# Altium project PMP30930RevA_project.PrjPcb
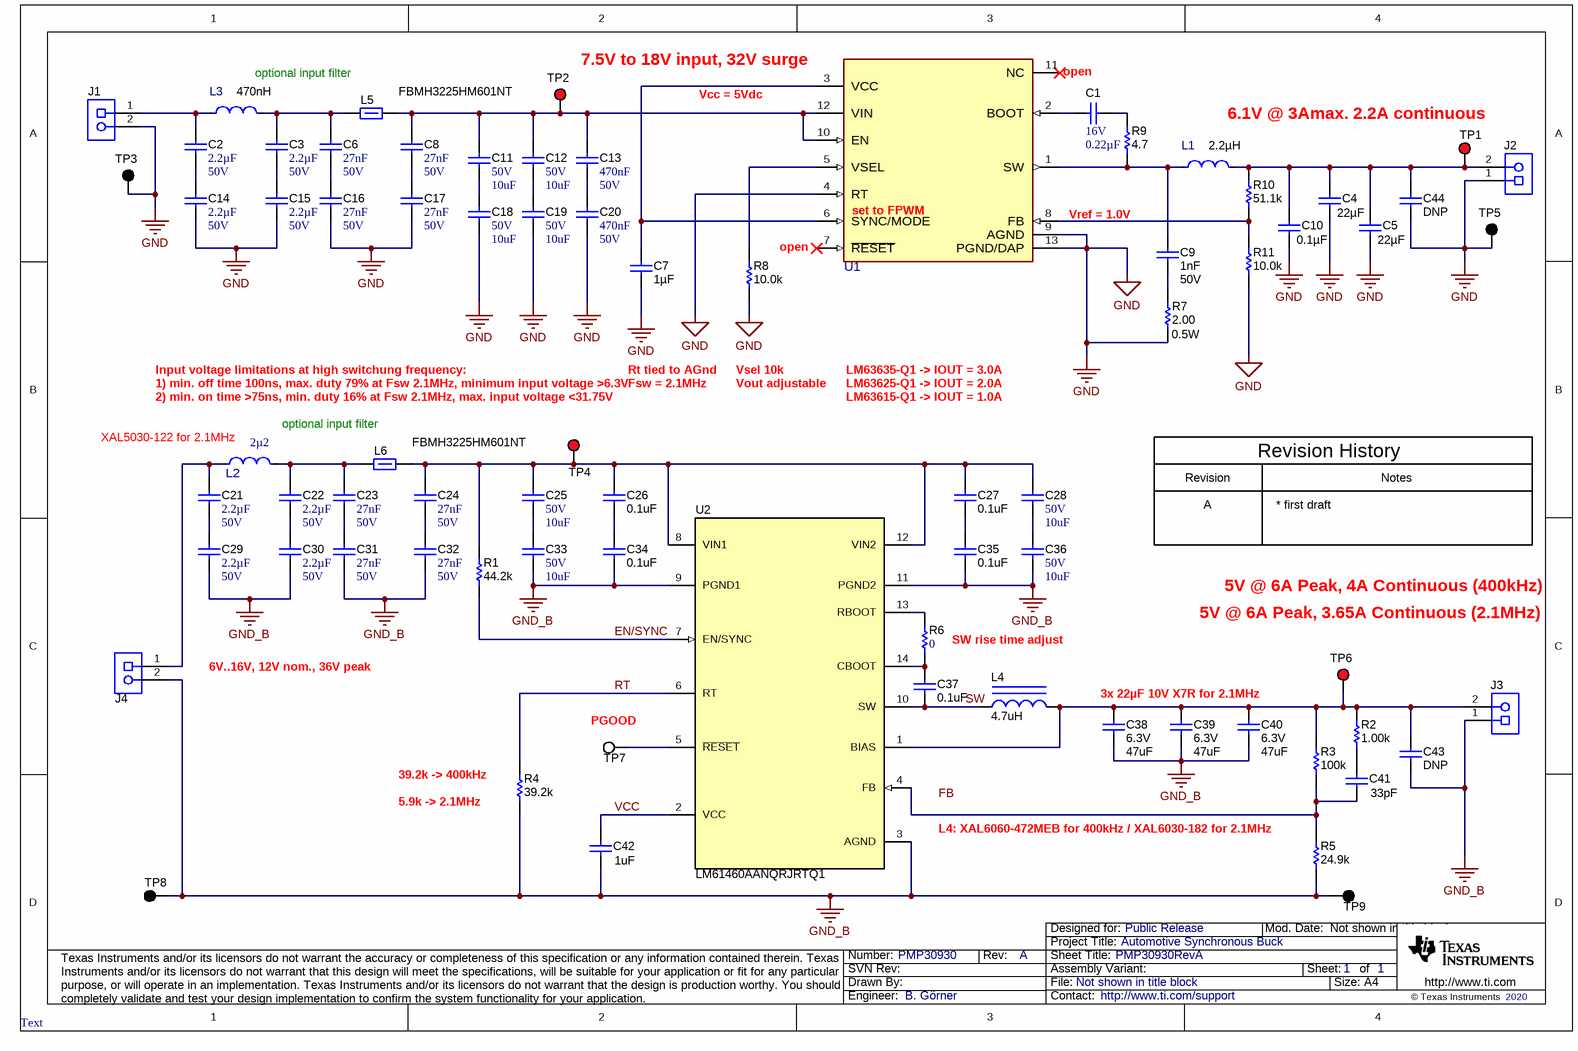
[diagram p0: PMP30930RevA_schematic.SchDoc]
CopyrightYear: 2020; PCB_Rev: A; PRJ_Customer: Public Release; PRJ_Engineer: B. Görner; PRJ_Number: PMP30930; PRJ_Title: Automotive Synchronous Buck; SCH_Rev: A; SCH_Title: asdf; TechSupport: http://www.ti.com/support; TID: N/A
2 sheets, 112 parts. Net scope: global (net labels, ports and power ports of the same name join across sheets).
Board file: PMP30930RevA_board.PcbDoc
Sheets:
  PMP30930RevA_schematic.SchDoc
  PMP30930RevA_schematic_2.SchDoc

## Sheet PMP30930RevA_schematic.SchDoc: PMP30930RevA
size A4; Date: Not shown in title block; ApprovedBy: Not shown in title block; CheckedBy: Not shown in title block; Author: Not shown in title block; CompanyName: Not shown in title block; Engineer: Not shown in title block; Organization: Not shown in title block; Address1: Not shown in title block; Address2: Not shown in title block; Address3: Not shown in title block; Address4: Not shown in title block; DocumentNumber: 1; Revision: Use project parameter SCH_Rev; SheetNumber: 1; SheetTotal: 1; PageSetup: Record=PageOptions¦CenterHorizontal=True¦CenterVertical=True¦PrintScale=0.70¦XCorrection=1.00¦YCorrection=1.00¦PrintKind=0¦BorderSize=5000000¦LeftOffset=0¦BottomOffset=0¦Orientation=2¦PaperLength=1000¦PaperWidth=1000¦Scale=100¦PaperSource=15¦PrintQuality=600¦MediaType=1¦DitherType=10¦PaperKind=A4¦PrintScaleMode=1

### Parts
C1  VDC_V: 16V  ValueDisplayed: 0.22µF  [0402]  (hidden comment: GCM155R71C224KE02D)
C2  Cap_F: 2.2µF  VDC_V: 50V  [0805_HV]  (hidden comment: CGA4J3X7R1H225K125AB)
C3  Cap_F: 2.2µF  VDC_V: 50V  [0805_HV]  (hidden comment: CGA4J3X7R1H225K125AB)
C4  ValueDisplayed: 22µF  [1210_270]  (hidden comment: GRM32ER71E226KE15L)
C5  ValueDisplayed: 22µF  [1210_270]  (hidden comment: GRM32ER71E226KE15L)
C6  Cap_F: 27nF  VDC_V: 50V  [0603]  (hidden comment: 06035C273K4T2A)
C7  ValueDisplayed: 1µF  [0603]  (hidden comment: GCM188R71E105KA64D)
C8  Cap_F: 27nF  VDC_V: 50V  [0603]  (hidden comment: 06035C273K4T2A)
C9  Cap_F: 1nF  VDC_V: 50V  [0603]  (hidden comment: GRM188R71H102KA01D)
C10  ValueDisplayed: 0.1µF  [0603]  (hidden comment: GRM188R71E104KA01D)
C11  VDC_V: 50V  ValueDisplayed: 10uF  [1210_270]  (hidden comment: GRM32ER71H106KA12L)
C12  VDC_V: 50V  ValueDisplayed: 10uF  [1210_270]  (hidden comment: GRM32ER71H106KA12L)
C13  Cap_F: 470nF  VDC_V: 50V  [0603]  (hidden comment: CGA3E3X7R1H474K080AE)
C14  Cap_F: 2.2µF  VDC_V: 50V  [0805_HV]  (hidden comment: CGA4J3X7R1H225K125AB)
C15  Cap_F: 2.2µF  VDC_V: 50V  [0805_HV]  (hidden comment: CGA4J3X7R1H225K125AB)
C16  Cap_F: 27nF  VDC_V: 50V  [0603]  (hidden comment: 06035C273K4T2A)
C17  Cap_F: 27nF  VDC_V: 50V  [0603]  (hidden comment: 06035C273K4T2A)
C18  VDC_V: 50V  ValueDisplayed: 10uF  [1210_270]  (hidden comment: GRM32ER71H106KA12L)
C19  VDC_V: 50V  ValueDisplayed: 10uF  [1210_270]  (hidden comment: GRM32ER71H106KA12L)
C20  Cap_F: 470nF  VDC_V: 50V  [0603]  (hidden comment: CGA3E3X7R1H474K080AE)
C21  Cap_F: 2.2µF  VDC_V: 50V  [0805_HV]  (hidden comment: CGA4J3X7R1H225K125AB)
C22  Cap_F: 2.2µF  VDC_V: 50V  [0805_HV]  (hidden comment: CGA4J3X7R1H225K125AB)
C23  Cap_F: 27nF  VDC_V: 50V  [0603]  (hidden comment: 06035C273K4T2A)
C24  Cap_F: 27nF  VDC_V: 50V  [0603]  (hidden comment: 06035C273K4T2A)
C25  VDC_V: 50V  ValueDisplayed: 10uF  [1210_270]  (hidden comment: GRM32ER71H106KA12L)
C26  ValueDisplayed: 0.1uF  [0402S]  (hidden comment: CGA2B3X7R1H104K050BB)
C27  ValueDisplayed: 0.1uF  [0402S]  (hidden comment: CGA2B3X7R1H104K050BB)
C28  VDC_V: 50V  ValueDisplayed: 10uF  [1210_270]  (hidden comment: GRM32ER71H106KA12L)
C29  Cap_F: 2.2µF  VDC_V: 50V  [0805_HV]  (hidden comment: CGA4J3X7R1H225K125AB)
C30  Cap_F: 2.2µF  VDC_V: 50V  [0805_HV]  (hidden comment: CGA4J3X7R1H225K125AB)
C31  Cap_F: 27nF  VDC_V: 50V  [0603]  (hidden comment: 06035C273K4T2A)
C32  Cap_F: 27nF  VDC_V: 50V  [0603]  (hidden comment: 06035C273K4T2A)
C33  VDC_V: 50V  ValueDisplayed: 10uF  [1210_270]  (hidden comment: GRM32ER71H106KA12L)
C34  ValueDisplayed: 0.1uF  [0402S]  (hidden comment: CGA2B3X7R1H104K050BB)
C35  ValueDisplayed: 0.1uF  [0402S]  (hidden comment: CGA2B3X7R1H104K050BB)
C36  VDC_V: 50V  ValueDisplayed: 10uF  [1210_270]  (hidden comment: GRM32ER71H106KA12L)
C37  ValueDisplayed: 0.1uF  [0402S]  (hidden comment: C0402C104K4RACAUTO)
C38  VDC_V: 6.3V  ValueDisplayed: 47uF  [1210_270]  (hidden comment: GCM32ER70J476KE19L)
C39  VDC_V: 6.3V  ValueDisplayed: 47uF  [1210_270]  (hidden comment: GCM32ER70J476KE19L)
C40  VDC_V: 6.3V  ValueDisplayed: 47uF  [1210_270]  (hidden comment: GCM32ER70J476KE19L)
C41  ValueDisplayed: 33pF  [0402S]  (hidden comment: C0402C330J5GACAUTO)
C42  ValueDisplayed: 1uF  [0603S]  (hidden comment: GCM188R71C105KA64D)
C43  ValueDisplayed: DNP  [0402S]  (hidden comment: CGA2B3X7R1H104K050BB)
C44  ValueDisplayed: DNP  [0402S]  (hidden comment: CGA2B3X7R1H104K050BB)
J1  ED555/2DS  [TERM_BLK_ED555-2DS]  (value not drawn)
J2  ED555/2DS  [TERM_BLK_ED555-2DS]  (value not drawn)
J3  ED555/2DS  [TERM_BLK_ED555-2DS]  (value not drawn)
J4  ED555/2DS  [TERM_BLK_ED555-2DS]  (value not drawn)
L1  Ind_H: 2.2µH  [FP-XGL4020-222MEC_SMT_4MM0_4MM0-MFG]  (hidden comment: XGL4020-222MEC)
L2  XEL5030-222MEB  [FP-XEL5030-222MEB_SMT_INDUCTOR_5MM28_5MM48-MFG]  (value not drawn)
L3  Ind_H: 470nH  [FP-XGL4020-471MEC_SMT_4MM0_4MM0-MFG]  (hidden comment: XGL4020-471MEC)
L4  ValueDisplayed: 4.7uH  [XAL6060]  (hidden comment: XAL6060-472MEB)
L5  FBMH3225HM601NT  [1210_280]
L6  FBMH3225HM601NT  [1210_280]
R1  ValueDisplayed: 44.2k  [0402S]  (hidden comment: CRCW040244K2FKED)
R2  ValueDisplayed: 1.00k  [0402S]  (hidden comment: CRCW04021K00FKED)
R3  ValueDisplayed: 100k  [0402S]  (hidden comment: RMCF0402FT100K)
R4  ValueDisplayed: 39.2k  [0402S]  (hidden comment: CRCW040239K2FKED)
R5  ValueDisplayed: 24.9k  [0402S]  (hidden comment: CRCW040224K9FKED)
R6  ValueDisplayed: 0  [0402S]  (hidden comment: CRCW04020000Z0EDHP)
R7  ValueDisplayed: 2.00  Value2: 0.5W  [0805_HV]  (hidden comment: CRCW08052R00FKEAHP)
R8  ValueDisplayed: 10.0k  [0402]  (hidden comment: CRCW040210K0FKED)
R9  ValueDisplayed: 4.7  [0603]  (hidden comment: CRCW06034R70JNEA)
R10  ValueDisplayed: 51.1k  [0402]  (hidden comment: CRCW040251K1FKED)
R11  ValueDisplayed: 10.0k  [0402]  (hidden comment: CRCW040210K0FKED)
TP1  5010  [Keystone5010]  (value not drawn)
TP2  5010  [Keystone5010]  (value not drawn)
TP3  5011  [Keystone5011]  (value not drawn)
TP4  5010  [Keystone5010]  (value not drawn)
TP5  5011  [Keystone5011]  (value not drawn)
TP6  5010  [Keystone5010]  (value not drawn)
TP7  5012  [Keystone5012]  (value not drawn)
TP8  5011  [Keystone5011]  (value not drawn)
TP9  5011  [Keystone5011]  (value not drawn)
U1  LM63635DQDRRRQ1  [DRR0012E-MFG]  (value not drawn)
U2  LM61460AANQRJRTQ1  [RJR0014A]

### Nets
GND: C4.2 C5.2 C7.2 C10.2 C14.2 C15.2 C16.2 C17.2 C18.2 C19.2 C20.2 C44.2 J1.2 J2.1 R7.2 R8.1 R11.1 TP3.1 TP5.1 U1.4(RT) U1.9(AGND) U1.13(PGND/DAP)
GND_B: C29.2 C30.2 C31.2 C32.2 C33.2 C34.2 C35.2 C36.2 C38.2 C39.2 C40.2 C42.2 C43.2 J3.1 J4.2 R4.1 R5.1 TP8.1 TP9.1 U2.3(AGND) U2.9(PGND1) U2.11(PGND2)
EN/SYNC: R1.1 U2.7(EN/SYNC)
RT: R4.2 U2.6(RT)
SW: C37.2 L4.1 U2.10(SW)
VCC: C42.1 U2.2(VCC)
NetC1_1: C1.1 R9.2
NetC1_2: C1.2 U1.2(BOOT)
NetC2_1: C2.1 J1.1 L3.1
NetC2_2: C2.2 C14.1
NetC3_1: C3.1 C6.1 L3.2 L5.1
NetC3_2: C3.2 C15.1
NetC4_1: C4.1 C5.1 C10.1 C44.1 J2.2 L1.2 R10.2 TP1.1
NetC6_2: C6.2 C16.1
NetC7_1: C7.1 U1.3(VCC) U1.6(SYNC/MODE)
NetC8_1: C8.1 C11.1 C12.1 C13.1 L5.2 TP2.1 U1.10(EN) U1.12(VIN)
NetC8_2: C8.2 C17.1
NetC9_1: C9.1 L1.1 R9.1 U1.1(SW)
NetC9_2: C9.2 R7.1
NetC11_2: C11.2 C18.1
NetC12_2: C12.2 C19.1
NetC13_2: C13.2 C20.1
NetC21_1: C21.1 J4.1 L2.1
NetC21_2: C21.2 C29.1
NetC22_1: C22.1 C23.1 L2.2 L6.1
NetC22_2: C22.2 C30.1
NetC23_2: C23.2 C31.1
NetC24_1: C24.1 C25.1 C26.1 C27.1 C28.1 L6.2 R1.2 TP4.1 U2.8(VIN1) U2.12(VIN2)
NetC24_2: C24.2 C32.1
NetC25_2: C25.2 C33.1
NetC26_2: C26.2 C34.1
NetC27_2: C27.2 C35.1
NetC28_2: C28.2 C36.1
NetC37_1: C37.1 R6.1 U2.14(CBOOT)
NetC38_1: C38.1 C39.1 C40.1 C43.1 J3.2 L4.2 R2.2 R3.2 TP6.1 U2.1(BIAS)
NetC41_1: C41.1 R2.1
NetC41_2: C41.2 R3.1 R5.2 U2.4(FB)
NetR6_2: R6.2 U2.13(RBOOT)
NetR8_2: R8.2 U1.5(VSEL)
NetR10_1: R10.1 R11.2 U1.8(FB)
NetTP7_1: TP7.1 U2.5(~{RESET})

Not connected (* = marked no-connect by the designer): U1 7(~{RESET})* 11(NC)*

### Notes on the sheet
- optional input filter
- 7.5V to 18V input, 32V surge
- Vcc = 5Vdc
- open
- 6.1V @ 3Amax. 2.2A continuous
- (near U1) set to FPWM
- Vref = 1.0V
- 1) min. off time 100ns, max. duty 79% at Fsw 2.1MHz, minimum input voltage >6.3V
- Input voltage limitations at high switchung frequency:
- Rt tied to AGnd
- Fsw = 2.1MHz
- Vsel 10k
- Vout adjustable
- LM63635-Q1 -> IOUT = 3.0A
- LM63625-Q1 -> IOUT = 2.0A
- 2) min. on time >75ns, min. duty 16% at Fsw 2.1MHz, max. input voltage <31.75V
- (near L2) XAL5030-122 for 2.1MHz
- (near L2) 2µ2
- LM63615-Q1 -> IOUT = 1.0A
- Revision History
- Revision
- A
- * first draft
- Notes
- 5V @ 6A Peak, 4A Continuous (400kHz)
- SW rise time adjust
- 5V @ 6A Peak, 3.65A Continuous (2.1MHz)
- 6V..16V, 12V nom., 36V peak
- (near TP7) PGOOD
- 3x 22µF 10V X7R for 2.1MHz
- (near R4) 39.2k -> 400kHz
- (near R4) 5.9k -> 2.1MHz
- L4: XAL6060-472MEB for 400kHz / XAL6030-182 for 2.1MHz
- Text
- Labels drawn without touching a wire or pin: FB

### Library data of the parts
C1 = CMP-0078265-1: CAP, CERM, 0.22 µF, 16 V,+/- 10%, X7R, AEC-Q200 Grade 1, 0402; Manufacturer: MuRata; TaMin_C: -55°C; Polarized: N; SizeAreaWB_mm2: 3; U/M: EA; Value: 0.22uF; TaMax_C: 125°C; SizeZ_mm: 0.6; SizeX_mm: 1; SizeY_mm: 0.5; AEC Qualified: Y; Cap_F: 220nF; AEC Category: Q200
C2 C3 C14 C15 C21 C22 C29 C30 = CMP-0007977-2: CAP, CERM, 2.2 uF, 50 V, +/- 10%, X7R, AEC-Q200 Grade 1, 0805; Manufacturer: TDK; TaMin_C: -55°C; ESR_ohm: 3.288m; Polarized: N; SizeAreaWB_mm2: 6.75; Value1: 0.003288 ohm; U/M: EA; Value: 2.2uF; TaMax_C: 125°C; SizeZ_mm: 1.45; SizeX_mm: 2; SizeY_mm: 1.25; Cap_Case: 0805; SizeArea_mm2: 2.5; AEC Qualified: Y; IRMS_A: 3.6003A; AEC Grade: 1; AEC Category: Q200
C4 C5 = GRM32ER71E226KE15L: CAP, CERM, 22 µF, 25 V,+/- 10%, X7R, 1210; Manufacturer: MuRata; Polarized: N; CompType: Capacitor; Value: 22uF; U/M: EA; Cap_F: 0.000022; Tolerance_%: 10; ESR_ohm: 0.002334; Value1: 0.002334 ohm; VDC_V: 25; Value2: 25V; IRMS_A: 3.832999; TaMin_C: -55; TaMax_C: 125; Cap_Case: 1210; SizeArea_mm2: 8; SizeAreaWB_mm2: 14.7; SizeX_mm: 3.2; SizeY_mm: 2.5; SizeZ_mm: 2.7; AEC Category: Q200; Green_Lifecycle: Active; Green_REACh: Passed
C6 C8 C16 C17 C23 C24 C31 C32 = CMP-0006804-3: CAP, CERM, 0.027 uF, 50 V, +/- 10%, X7R, AEC-Q200 Grade 1, 0603; Manufacturer: AVX; TaMin_C: -55°C; Polarized: N; SizeAreaWB_mm2: 4.68; Value1: Unknown; U/M: EA; TaMax_C: 125°C; SizeZ_mm: 1; SizeX_mm: 1.6; SizeY_mm: 0.8; SizeArea_mm2: 1.28; AEC Qualified: Y; AEC Category: Q200
C7 = GCM188R71E105KA64D: CAP, CERM, 1 µF, 25 V,+/- 10%, X7R, AEC-Q200 Grade 1, 0603; Manufacturer: MuRata; Polarized: N; CompType: Capacitor; Value: 1uF; U/M: EA; Cap_F: 0.000001; Tolerance_%: 10; VDC_V: 25; Value2: 25V; TaMin_C: -55; TaMax_C: 125; SizeArea_mm2: 1.28; SizeAreaWB_mm2: 4.68; SizeX_mm: 1.6; SizeY_mm: 0.8; SizeZ_mm: 1; AEC Category: Q200; AEC Qualified: Y
C9 = CMP-0007432-5: CAP, CERM, 1000 pF, 50 V, +/- 10%, X7R, 0603; Manufacturer: MuRata; TaMin_C: -55°C; Polarized: N; SizeAreaWB_mm2: 4.68; Value1: Unknown; U/M: EA; Value: 1000pF; TaMax_C: 125°C; SizeZ_mm: 1; SizeX_mm: 1.6; SizeY_mm: 0.8; SizeArea_mm2: 1.28; AEC Category: Q200
C10 = GRM188R71E104KA01D: CAP, CERM, 0.1 µF, 25 V,+/- 10%, X7R, 0603; Manufacturer: MuRata; Polarized: N; CompType: Capacitor; Value: 0.1uF; U/M: EA; Cap_F: 0.0000001; Tolerance_%: 10; VDC_V: 25; Value2: 25V; TaMin_C: -55; TaMax_C: 125; SizeArea_mm2: 1.28; SizeAreaWB_mm2: 4.68; SizeX_mm: 1.6; SizeY_mm: 0.8; SizeZ_mm: 1; AEC Category: Q200; Green_Lifecycle: Active; Green_REACh: Passed
C11 C12 C18 C19 C25 C28 C33 C36 = CMP-0009226-3: CAP, CERM, 10 uF, 50 V, +/- 10%, X7R, 1210; Manufacturer: MuRata; TaMin_C: -55°C; Polarized: N; SizeAreaWB_mm2: 14.7; Value1: Unknown; U/M: EA; Value: 10uF; TaMax_C: 125°C; SizeZ_mm: 2.7; SizeX_mm: 3.2; SizeY_mm: 2.5; Cap_Case: 1210; SizeArea_mm2: 8; Cap_F: 10µF; AEC Category: Q200
C13 C20 = CMP-0007097-3: CAP, CERM, 0.47 uF, 50 V, +/- 10%, X7R, AEC-Q200 Grade 1, 0603; Manufacturer: TDK; TaMin_C: -55°C; Polarized: N; SizeAreaWB_mm2: 4.68; Value1: Unknown; U/M: EA; Value: 0.47uF; TaMax_C: 125°C; SizeZ_mm: 1; SizeX_mm: 1.6; SizeY_mm: 0.8; SizeArea_mm2: 1.28; AEC Qualified: Y; AEC Category: Q200
C26 C27 C34 C35 C43 C44 = CMP-0006325-2: CAP, CERM, 0.1 uF, 50 V, +/- 10%, X7R, AEC-Q200 Grade 1, 0402; Manufacturer: TDK; TaMin_C: -55°C; ESR_ohm: 0.039064; Polarized: N; SizeAreaWB_mm2: 3; Value1: 0.039064 ohm; U/M: EA; Value: 0.1uF; TaMax_C: 125°C; SizeZ_mm: 0.6; SizeX_mm: 1; SizeY_mm: 0.5; Cap_Case: 0402; Value2: 50V; AEC Qualified: Y; Cap_F: 100nF; IRMS_A: 814.669mA; AEC Category: Q200
C37 = CMP-0006237-1: CAP, CERM, 0.1 uF, 16 V, +/- 10%, X7R, AEC-Q200 Grade 1, 0402; Manufacturer: Kemet; TaMin_C: -55°C; Polarized: N; SizeAreaWB_mm2: 3; Value1: Unknown; U/M: EA; Value: 0.1uF; TaMax_C: 125°C; SizeZ_mm: 0.6; SizeX_mm: 1; SizeY_mm: 0.5; Cap_Case: 0402; Value2: 16V; AEC Qualified: Y; Cap_F: 100nF; AEC Category: Q200
C38-C40 = CMP-0009172-1: CAP, CERM, 47 uF, 6.3 V, +/- 10%, X7R, AEC-Q200 Grade 1, 1210; Manufacturer: MuRata; TaMin_C: -55°C; Polarized: N; SizeAreaWB_mm2: 14.7; Value1: Unknown; U/M: EA; Value: 47uF; TaMax_C: 125°C; SizeZ_mm: 2.7; SizeX_mm: 3.2; SizeY_mm: 2.5; Cap_Case: 1210; SizeArea_mm2: 8; AEC Qualified: Y; Cap_F: 47µF; AEC Grade: 1; AEC Category: Q200
C41 = CMP-0079151-1: CAP, CERM, 33 pF, 50 V,+/- 5%, C0G, AEC-Q200 Grade 1, 0402; Manufacturer: Kemet; SizeAreaWB_mm2: 3; SizeArea_mm2: 0.5; AEC Qualified: Y; AEC Category: Q200; Value: 33pF; TaMax_C: 125°C; SizeZ_mm: 0.6; AEC Grade: 1; Polarized: N; TaMin_C: -55°C; Value2: 50V; U/M: EA; Cap_Case: 0402
C42 = CMP-0007136-1: CAP, CERM, 1 uF, 16 V, +/- 10%, X7R, AEC-Q200 Grade 1, 0603; Manufacturer: MuRata; TaMin_C: -55°C; Polarized: N; SizeAreaWB_mm2: 4.68; Value1: Unknown; U/M: EA; Value: 1uF; TaMax_C: 125°C; SizeZ_mm: 1; SizeX_mm: 1.6; SizeY_mm: 0.8; Cap_Case: 0603; Value2: 16V; SizeArea_mm2: 1.28; AEC Qualified: Y; Cap_F: 1µF; AEC Category: Q200
J1-J4 = CMP-0074913-1: Terminal Block, 3.5mm Pitch, 2x1, TH; Manufacturer: On-Shore Technology; Cert_VDE: Y; CNHeader: False; Current_A: 6A; Green_Lifecycle: Active; Shrouded: N; Gender: Female; Green_REACh: Passed; Voltage_V: 150V; Row_Count: 1; Pitch_mm: 3.5; ContactFinish: Brass; CT: True
L1 = CMP-0086519-1: Shielded Power Inductors; Manufacturer: Coilcraft; AEC Grade: Grade 1; Symbol Name: SYM-XGL4020-222MEC; Isat: 2.7A; Irms: 8.9A; AEC Qualified: Yes; Material: Composite; DCR_ohm: 21.5; SizeZ_mm: 2.1mm
L2 = CMP-0089324-1: Shielded Power Inductor XEL5030; Manufacturer: Coilcraft; Material: Composite; AEC Qualified: Yes; DCR_ohm: 14.5m; Shrouded: true; Self Resonant Frequency: 36MHz; Irms: 9.7A; TaMin_C: -40°C; Test Frequency: 1MHz; Isat: 10.5A; Ind_H: 2.2µH; Tolerance_%: 20%; Standoff Height: 0.12mm; TaMax_C: +125°C; AEC Grade: Grade 1; SizeZ_mm: 3.1mm
L3 = CMP-0087242-1: Shielded Power Inductors; Manufacturer: Coilcraft; SizeZ_mm: 2.1mm; Symbol Name: SYM-XGL4020-471MEC; Isat: 6.1A; DCR_ohm: 5.1m; Material: Composite; Irms: 19.7A; AEC Grade: Grade 1; AEC Qualified: Yes
L4 = CMP-0061020-1: Inductor, Shielded, Composite, 4.7 uH, 10.5 A, 0.015 ohm, SMD; Manufacturer: Coilcraft; Isat: 10.5A @ 30% inductance drop; Irms: 12.3A @ 40C rise; Green_Lifecycle: Not Set; SizeAreaWB_mm2: 71.5616; DCR_ohm: 0.015; Green_REACh: Incomplete; Value: 4.7uH; Imax_A: 10.5A; SizeZ_mm: 6.1; SizeX_mm: 6.36; SizeY_mm: 6.56; SizeArea_mm2: 41.7216; Ind_H: 4.7µH; AEC Category: Q200
L5 L6 = CMP-0003374-1: Ferrite Bead, 600 ohm @ 100 MHz, 3 A, 1210; Manufacturer: Taiyo Yuden; ZTyp@100MHz_Ohm: 600; SizeAreaWB_mm2: 14.7; DCR_ohm: 42m; Value1: 0.042 ohm; Value: 600 ohm; Imax_A: 3A; SizeZ_mm: 2.8; SizeX_mm: 3.2; SizeY_mm: 2.5; SizeArea_mm2: 8
R1 = CMP-0026383-2: RES, 44.2 k, 1%, 0.063 W, AEC-Q200 Grade 0, 0402; Manufacturer: Vishay-Dale; Power_W: 63mW; TempCo: 100 ppm/C; Value_Code: 44k2; Value: 44.2k; EIA_Code: E96; SizeX_mm: 1; SizeY_mm: 0.5; SizeZ_mm: 0.6; Value2: 0.063W; AEC Qualified: Y; VDC_V: 50V; AEC Category: Q200; AEC Grade: 0
R2 = CMP-0026071-3: RES, 1.00 k, 1%, 0.063 W, AEC-Q200 Grade 0, 0402; Manufacturer: Vishay-Dale; Power_W: 63mW; TempCo: 100 ppm/C; Value_Code: 1k00; Value: 1.00k; EIA_Code: E96; Res_ohm: 1k; SizeX_mm: 1; SizeY_mm: 0.5; SizeZ_mm: 0.6; Value2: 0.063W; AEC Qualified: Y; VDC_V: 50V; AEC Category: Q200; AEC Grade: 0
R3 = CMP-0026753-1: RES, 100 k, 1%, 0.063 W, AEC-Q200 Grade 0, 0402; Manufacturer: Stackpole Electronics Inc; Power_W: 63mW; TempCo: 100 ppm/C; U/M: EA; Value: 100k; EIA_Code: E96; SizeX_mm: 1; SizeY_mm: 0.5; SizeZ_mm: 0.6; Value2: 0.063W; AEC Qualified: Y; VDC_V: 50V; AEC Grade: 0; AEC Category: Q200
R4 = CMP-0026327-2: RES, 39.2 k, 1%, 0.063 W, AEC-Q200 Grade 0, 0402; Manufacturer: Vishay-Dale; Power_W: 63mW; TempCo: 100 ppm/C; Value_Code: 39k2; Value: 39.2k; EIA_Code: E96; SizeX_mm: 1; SizeY_mm: 0.5; SizeZ_mm: 0.6; Value2: 0.063W; AEC Qualified: Y; VDC_V: 50V; AEC Category: Q200; AEC Grade: 0
R5 = CMP-0026196-2: RES, 24.9 k, 1%, 0.063 W, AEC-Q200 Grade 0, 0402; Manufacturer: Vishay-Dale; Power_W: 63mW; TempCo: 100 ppm/C; Value_Code: 24k9; Value: 24.9k; EIA_Code: E96; SizeX_mm: 1; SizeY_mm: 0.5; SizeZ_mm: 0.6; Value2: 0.063W; AEC Qualified: Y; VDC_V: 50V; AEC Category: Q200; AEC Grade: 0
R6 = CMP-0081856-1: RES, 0, 0%, 0.2 W, AEC-Q200 Grade 0, 0402; Manufacturer: Vishay-Dale; SizeAreaWB_mm2: 3; SizeArea_mm2: 0.5; AEC Qualified: Y; AEC Category: Q200; Value: 0; SizeZ_mm: 0.6; Power_W: 200mW; VDC_V: 50V; Value2: 0.2W; SizeX_mm: 1
R7 = CRCW08054R70FKEAHP: RES, 2.00, 1%, 0.5 W, AEC-Q200 Grade 0, 0805; Manufacturer: Vishay-Dale; CompType: Resistor; Value: 2.00; Value_Code: 2R00; Tolerance_%: 1; Power_W: 0.5; TempCo: 100 ppm/C; SizeArea_mm2: 2.5; SizeX_mm: 2; SizeY_mm: 1.25; SizeZ_mm: 1.45; U/M: EA; AEC Category: Q200; AEC Qualified: Y; AEC Grade: 0
R8 R11 = CRCW040210K0FKED: RES, 10.0 k, 1%, 0.063 W, 0402; Manufacturer: Vishay-Dale; CompType: Resistor; Value: 10.0k; Res_ohm: 10000; Value_Code: 10k0; Tolerance_%: 1; Power_W: 0.063; Value2: 0.063W; VDC_V: 50; TempCo: 100 ppm/C; SizeArea_mm2: 0.5; SizeZ_mm: 0.6; EIA_Code: E96; U/M: EA; AEC Category: Q200; Green_Lifecycle: Active; Green_REACh: Passed
R9 = CRCW06034R70JNEA: RES, 4.7, 5%, 0.1 W, 0603; Manufacturer: Vishay-Dale; CompType: Resistor; Value: 4.7; Value_Code: 4R70; Tolerance_%: 5; Power_W: 0.1; Value2: 0.1W; VDC_V: 75; TempCo: 200 ppm/C; SizeArea_mm2: 1.28; SizeX_mm: 1.6; SizeY_mm: 0.8; SizeZ_mm: 1; EIA_Code: E24; U/M: EA; AEC Category: Q200; Green_Lifecycle: Active; Green_REACh: Passed
R10 = CRCW040251K1FKED: RES, 51.1 k, 1%, 0.063 W, 0402; Manufacturer: Vishay-Dale; CompType: Resistor; Value: 51.1k; Res_ohm: 51100; Value_Code: 51k1; Tolerance_%: 1; Power_W: 0.063; Value2: 0.063W; VDC_V: 50; TempCo: 100 ppm/C; SizeArea_mm2: 0.5; SizeZ_mm: 0.6; EIA_Code: E96; U/M: EA; AEC Category: Q200; Green_Lifecycle: Active; Green_REACh: Passed
TP1 TP2 TP4 TP6 = CMP-0055147-1: Test Point, Multipurpose, Red, TH; Manufacturer: Keystone; CNHeader: FALSE; Green_Lifecycle: Active; Green_REACh: Passed; ContactFinish: Silver; CT: TRUE
TP3 TP5 TP8 TP9 = CMP-0055148-1: Test Point, Multipurpose, Black, TH; Manufacturer: Keystone; CNHeader: FALSE; Green_Lifecycle: Active; Green_REACh: Passed; ContactFinish: Silver; CT: TRUE
TP7 = CMP-0055149-1: Test Point, Multipurpose, White, TH; Manufacturer: Keystone; CNHeader: FALSE; Green_Lifecycle: Active; Green_REACh: Passed; ContactFinish: Silver; CT: TRUE
U1 = CMP-0088353-1: 3.5-V to 36-V, 1.5-A, and 2.5-A Automotive Step-down Voltage Converter; Manufacturer: Texas Instruments; Max Supply Voltage: 32V; Number Of Outputs: 1; Standoff Height: 0mm; Output Type: Fixed,AdjustableProgrammable; Switching Topology: Buck; TaMax_C: +125°C; Min Supply Voltage: 3.5V; Max Duty Cycle: 98%; TaMin_C: -40°C; AEC Qualified: Yes; Output Voltage: 3.3/5/1-20V; AEC Grade: Grade 1; TJmax_C: +150°C; Nominal Supply Current: 23uA; SizeZ_mm: 0.8mm; Switching Frequency: 400/2100/250-2200kHz
U2 = CMP-0079820-1: Automotive 6-A Low Noise Synchronous Buck Regulators, RJR0014A (VQFN-HR-14); Alternate Manufacturer: Texas Instruments; SizeAreaWB_mm2: 22.5; SizeZ_mm: 1; SizeX_mm: 4; SizeY_mm: 3.5; SizeArea_mm2: 14; CompType: IC; AEC Qualified: Y; AEC Category: Q200

## Sheet PMP30930RevA_schematic_2.SchDoc
size A4; Date: Not shown in title block; ApprovedBy: Not shown in title block; CheckedBy: Not shown in title block; Author: Not shown in title block; CompanyName: Not shown in title block; Engineer: Not shown in title block; Organization: Not shown in title block; Address1: Not shown in title block; Address2: Not shown in title block; Address3: Not shown in title block; Address4: Not shown in title block; DocumentNumber: 1; Revision: Use project parameter SCH_Rev; SheetNumber: 1; SheetTotal: 1; PageSetup: Record=PageOptions¦CenterHorizontal=True¦CenterVertical=True¦PrintScale=0.93¦XCorrection=1.00¦YCorrection=1.00¦PrintKind=0¦BorderSize=5000000¦LeftOffset=0¦BottomOffset=0¦Orientation=2¦PaperLength=1000¦PaperWidth=1000¦Scale=100¦PaperSource=15¦PrintQuality=600¦MediaType=1¦DitherType=10¦PaperKind=Letter¦PrintScaleMode=1
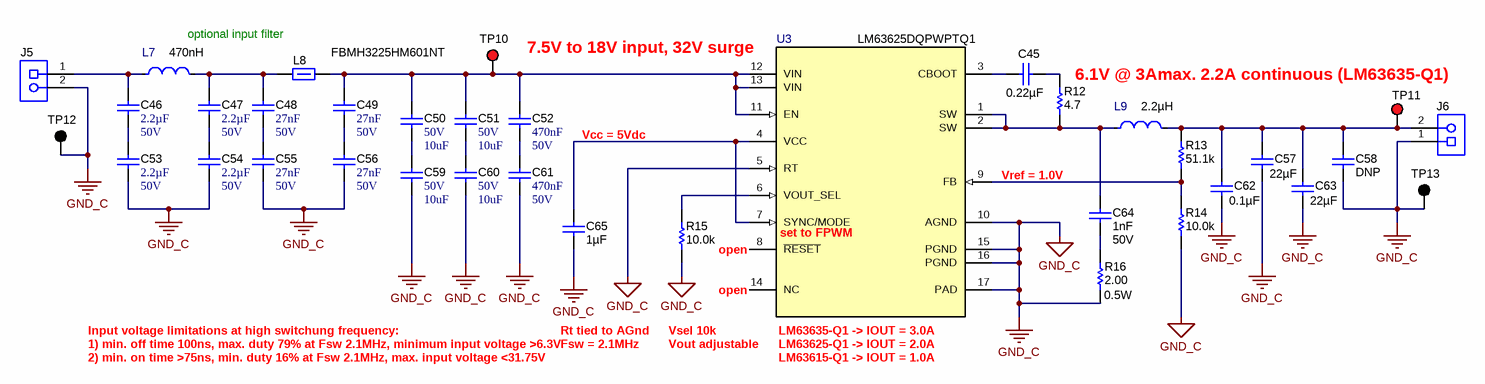
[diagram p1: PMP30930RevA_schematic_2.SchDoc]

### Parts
C45  ValueDisplayed: 0.22µF  [0603]  (hidden comment: GCM188R71H224KA64D)
C46  Cap_F: 2.2µF  VDC_V: 50V  [0805_HV]  (hidden comment: CGA4J3X7R1H225K125AB)
C47  Cap_F: 2.2µF  VDC_V: 50V  [0805_HV]  (hidden comment: CGA4J3X7R1H225K125AB)
C48  Cap_F: 27nF  VDC_V: 50V  [0603]  (hidden comment: 06035C273K4T2A)
C49  Cap_F: 27nF  VDC_V: 50V  [0603]  (hidden comment: 06035C273K4T2A)
C50  VDC_V: 50V  ValueDisplayed: 10uF  [1210_270]  (hidden comment: GRM32ER71H106KA12L)
C51  VDC_V: 50V  ValueDisplayed: 10uF  [1210_270]  (hidden comment: GRM32ER71H106KA12L)
C52  Cap_F: 470nF  VDC_V: 50V  [0603]  (hidden comment: CGA3E3X7R1H474K080AE)
C53  Cap_F: 2.2µF  VDC_V: 50V  [0805_HV]  (hidden comment: CGA4J3X7R1H225K125AB)
C54  Cap_F: 2.2µF  VDC_V: 50V  [0805_HV]  (hidden comment: CGA4J3X7R1H225K125AB)
C55  Cap_F: 27nF  VDC_V: 50V  [0603]  (hidden comment: 06035C273K4T2A)
C56  Cap_F: 27nF  VDC_V: 50V  [0603]  (hidden comment: 06035C273K4T2A)
C57  ValueDisplayed: 22µF  [1210_270]  (hidden comment: GRM32ER71E226KE15L)
C58  ValueDisplayed: DNP  [0402S]  (hidden comment: CGA2B3X7R1H104K050BB)
C59  VDC_V: 50V  ValueDisplayed: 10uF  [1210_270]  (hidden comment: GRM32ER71H106KA12L)
C60  VDC_V: 50V  ValueDisplayed: 10uF  [1210_270]  (hidden comment: GRM32ER71H106KA12L)
C61  Cap_F: 470nF  VDC_V: 50V  [0603]  (hidden comment: CGA3E3X7R1H474K080AE)
C62  ValueDisplayed: 0.1µF  [0603]  (hidden comment: GRM188R71E104KA01D)
C63  ValueDisplayed: 22µF  [1210_270]  (hidden comment: GRM32ER71E226KE15L)
C64  Cap_F: 1nF  VDC_V: 50V  [0603]  (hidden comment: GRM188R71H102KA01D)
C65  ValueDisplayed: 1µF  [0603]  (hidden comment: GCM188R71E105KA64D)
J5  ED555/2DS  [TERM_BLK_ED555-2DS]  (value not drawn)
J6  ED555/2DS  [TERM_BLK_ED555-2DS]  (value not drawn)
L7  Ind_H: 470nH  [FP-XGL4020-471MEC_SMT_4MM0_4MM0-MFG]  (hidden comment: XGL4020-471MEC)
L8  FBMH3225HM601NT  [1210_280]
L9  Ind_H: 2.2µH  [FP-XGL4020-222MEC_SMT_4MM0_4MM0-MFG]  (hidden comment: XGL4020-222MEC)
R12  ValueDisplayed: 4.7  [0603]  (hidden comment: CRCW06034R70JNEA)
R13  ValueDisplayed: 51.1k  [0402]  (hidden comment: CRCW040251K1FKED)
R14  ValueDisplayed: 10.0k  [0402]  (hidden comment: CRCW040210K0FKED)
R15  ValueDisplayed: 10.0k  [0402]  (hidden comment: CRCW040210K0FKED)
R16  ValueDisplayed: 2.00  Value2: 0.5W  [0805_HV]  (hidden comment: CRCW08052R00FKEAHP)
TP10  5010  [Keystone5010]  (value not drawn)
TP11  5010  [Keystone5010]  (value not drawn)
TP12  5011  [Keystone5011]  (value not drawn)
TP13  5011  [Keystone5011]  (value not drawn)
U3  LM63625DQPWPTQ1  [PWP0016K_N]

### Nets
GND_C: C53.2 C54.2 C55.2 C56.2 C57.2 C58.2 C59.2 C60.2 C61.2 C62.2 C63.2 C65.2 J5.2 J6.1 R14.1 R15.1 R16.2 TP12.1 TP13.1 U3.5(RT) U3.10(AGND) U3.15(PGND) U3.16(PGND) U3.17(PAD)
NetC45_1: C45.1 R12.2
NetC45_2: C45.2 U3.3(CBOOT)
NetC46_1: C46.1 J5.1 L7.1
NetC46_2: C46.2 C53.1
NetC47_1: C47.1 C48.1 L7.2 L8.1
NetC47_2: C47.2 C54.1
NetC48_2: C48.2 C55.1
NetC49_1: C49.1 C50.1 C51.1 C52.1 L8.2 TP10.1 U3.11(EN) U3.12(VIN) U3.13(VIN)
NetC49_2: C49.2 C56.1
NetC50_2: C50.2 C59.1
NetC51_2: C51.2 C60.1
NetC52_2: C52.2 C61.1
NetC57_1: C57.1 C58.1 C62.1 C63.1 J6.2 L9.2 R13.2 TP11.1
NetC64_1: C64.1 L9.1 R12.1 U3.1(SW) U3.2(SW)
NetC64_2: C64.2 R16.1
NetC65_1: C65.1 U3.4(VCC) U3.7(SYNC/MODE)
NetR13_1: R13.1 R14.2 U3.9(FB)
NetR15_2: R15.2 U3.6(VOUT_SEL)

Not connected (* = marked no-connect by the designer): U3 8(~{RESET}) 14(NC)

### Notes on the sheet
- optional input filter
- 7.5V to 18V input, 32V surge
- 6.1V @ 3Amax. 2.2A continuous (LM63635-Q1)
- Vcc = 5Vdc
- (near U3) set to FPWM
- Vref = 1.0V
- open
- (near U3) open
- 1) min. off time 100ns, max. duty 79% at Fsw 2.1MHz, minimum input voltage >6.3V
- 2) min. on time >75ns, min. duty 16% at Fsw 2.1MHz, max. input voltage <31.75V
- Input voltage limitations at high switchung frequency:
- Rt tied to AGnd
- Fsw = 2.1MHz
- Vsel 10k
- (near U3) Vout adjustable
- (near U3) LM63635-Q1 -> IOUT = 3.0A
- LM63615-Q1 -> IOUT = 1.0A
- (near U3) LM63625-Q1 -> IOUT = 2.0A

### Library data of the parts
C45 = GCM188R71H224KA64D: CAP, CERM, 0.22 µF, 50 V,+/- 10%, X7R, AEC-Q200 Grade 1, 0603; Manufacturer: MuRata; Polarized: N; CompType: Capacitor; Value: 0.22uF; U/M: EA; Cap_F: 0.00000022; Tolerance_%: 10; VDC_V: 50; Value2: 50V; TaMin_C: -55; TaMax_C: 125; SizeArea_mm2: 1.28; SizeAreaWB_mm2: 4.68; SizeX_mm: 1.6; SizeY_mm: 0.8; SizeZ_mm: 1; AEC Category: Q200; AEC Qualified: Y; Green_Lifecycle: Active; Green_REACh: Passed
C46 C47 C53 C54 = CMP-0007977-2: as C2 on sheet PMP30930RevA_schematic
C48 C49 C55 C56 = CMP-0006804-3: as C6 on sheet PMP30930RevA_schematic
C50 C51 C59 C60 = CMP-0009226-3: as C11 on sheet PMP30930RevA_schematic
C52 C61 = CMP-0007097-3: as C13 on sheet PMP30930RevA_schematic
C57 C63 = GRM32ER71E226KE15L: as C4 on sheet PMP30930RevA_schematic
C58 = CMP-0006325-2: as C26 on sheet PMP30930RevA_schematic
C62 = GRM188R71E104KA01D: as C10 on sheet PMP30930RevA_schematic
C64 = CMP-0007432-5: as C9 on sheet PMP30930RevA_schematic
C65 = GCM188R71E105KA64D: as C7 on sheet PMP30930RevA_schematic
J5 J6 = CMP-0074913-1: as J1 on sheet PMP30930RevA_schematic
L7 = CMP-0087242-1: as L3 on sheet PMP30930RevA_schematic
L8 = CMP-0003374-1: as L5 on sheet PMP30930RevA_schematic
L9 = CMP-0086519-1: as L1 on sheet PMP30930RevA_schematic
R12 = CRCW06034R70JNEA: as R9 on sheet PMP30930RevA_schematic
R13 = CRCW040251K1FKED: as R10 on sheet PMP30930RevA_schematic
R14 R15 = CRCW040210K0FKED: as R8 on sheet PMP30930RevA_schematic
R16 = CRCW08054R70FKEAHP: as R7 on sheet PMP30930RevA_schematic
TP10 TP11 = CMP-0055147-1: as TP1 on sheet PMP30930RevA_schematic
TP12 TP13 = CMP-0055148-1: as TP3 on sheet PMP30930RevA_schematic
U3 = CMP-0080080-4: 3.5-V to 36-V, 2.5-A Synchronous Step-Down Voltage Regulator with Spread Spectrum, PWP0016D (TSSOP-16); Alternate Manufacturer: Texas Instruments; SizeAreaWB_mm2: 58.8; SizeZ_mm: 1.2; SizeX_mm: 6.4; SizeY_mm: 5; SizeArea_mm2: 32; CompType: IC; AEC Qualified: Y; AEC Category: Q200; Rating: Automotive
